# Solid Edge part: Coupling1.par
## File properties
Author: f_grande
Template: Normal.par
Last saved by: f_grande
Revision: 3
Application: Solid Edge
Material: Acciaio
Stile della faccia: Acciaio
Stile di riempimento: ANSI32(Acciaio)
Stile virtuale: Acciaio lavorato a macchina
Coef. of Thermal Exp: 0.0
Thermal Conductivity: 32.0
Specific Heat: 481.0
Modulus of Elasticity: 199947953000.0
Poisson's Ratio: 0.29
Yield Stress: 262000766.0
Ultimate Stress: 358527364.0
Elongation: 0.0
Tipo di contenuto documento: 0
Densità: 7833,000 kg/m^3
Precisione: 0,990
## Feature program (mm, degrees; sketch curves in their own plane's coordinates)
sketch for "unnamed Protrusion 1" plane through (0, 0, 0) normal (0, 0, 1) x-axis (1, 0, 0)
  circle centre (0, 0) radius 13.75
extrude "unnamed Protrusion 1" add finite 27 along +normal
sketch for "ExtrudedCutout_1" plane through (0, 0, 27) normal (0, 0, 1) x-axis (1, 0, 0)
  line (-3.5923, 7.7036) -> (-5.811, 12.4617)
  arc centre (0, 0) radius 13.75 from (-5.811, -12.4617) to (-5.811, 12.4617) cw
  line (-3.5923, -7.7036) -> (-5.811, -12.4617)
  arc centre (0, 0) radius 8.5 from (3.5923, -7.7036) to (-3.5923, -7.7036) cw
  line (3.5923, -7.7036) -> (5.811, -12.4617)
  line (3.5923, 7.7036) -> (5.811, 12.4617)
extrude "ExtrudedCutout_1" cut finite 10 along -normal
fillet "Rotondo_1" radius 0.5
sketch for "Foro_1" plane through (0, 0, 0) normal (0, 0, -1) x-axis (0, 1, 0)
  hole centre (0, 0) bore radius 5
hole "Foro_1" diameter 10 through
chamfer "Smusso_1" setback 1
chamfer "Smusso_2" setback 1
sketch for "Foro_2" plane through (-36.3442, 0, 0) normal (1, 0, 0) x-axis (0, 1, 0)
  hole centre (0, 8.1899) bore radius 1.621
hole "Foro_2" nominal diameter 4 through  ThreadDepth = 2 mm
chamfer "Smusso_3" setback 0.5
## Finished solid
Body 1: solid body, 43 faces, 87 edges, 44 vertices.
  Faces by surface: cylinder 17, plane 8, sphere 8, torus 7, cone 2, spline 1
  Edges by curve: circle 52, line 28, intersection 5, curve on surface 2
Bounding box of the edges (mm; curved faces can reach further): 27.500 x 27.500 x 27.000, from (-13.75, -13.75, 0) to (13.75, 13.75, 27).
Cylindrical faces by radius (mm): R0.5 x12, R1.621 x1, R5 x1, R8.5 x2, R13.75 x1
Conical faces (half-angle, radius in mm at the cone's reference point): 45 deg R5 x1, 45 deg R6 x1
Toroidal faces (ring radius, tube radius in mm): R9 r0.5 x2, R13.25 r0.5 x5
Spherical faces by radius (mm): R0.5 x8
Planar faces by outward normal: +z 3, -z 1, oblique 4
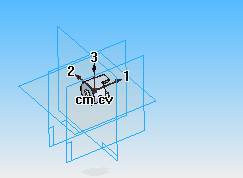
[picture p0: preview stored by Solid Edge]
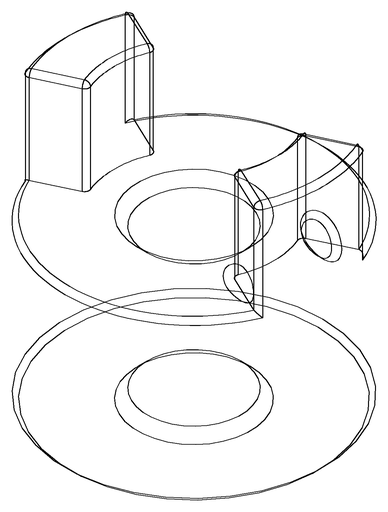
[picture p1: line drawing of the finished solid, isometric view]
